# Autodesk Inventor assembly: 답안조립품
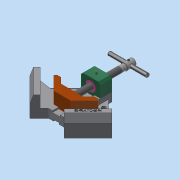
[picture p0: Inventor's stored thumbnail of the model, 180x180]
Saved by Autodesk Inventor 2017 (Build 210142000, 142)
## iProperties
Part Number: 답안조립품
Material: 일반
Document SubType Name: Assembly
Designer: 222
Author: 222
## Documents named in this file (11)
- C:\Users\222\Desktop\700506V1054\답안조립품.iam
- C:\Users\222\Desktop\700506V1054\본체.ipt
- C:\Users\222\Desktop\700506V1054\리드스크류.ipt
- C:\Users\222\Desktop\700506V1054\멈춤나사 M4x5.ipt
- C:\Users\222\Desktop\700506V1054\멈춤나사 M4x10.ipt
- C:\Users\222\Desktop\700506V1054\볼트 M4x16.ipt
- C:\Users\222\Desktop\700506V1054\부시.ipt
- C:\Users\222\Desktop\700506V1054\서포트.ipt
- C:\Users\222\Desktop\700506V1054\조.ipt
- C:\Users\222\Desktop\700506V1054\평행 핀 2.5x24.ipt
- C:\Users\222\Desktop\700506V1054\핸들.ipt
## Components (1 placed, 1 different names)
1. 핸들:1 — 각도:1
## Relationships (1: Angle 1)
- 각도:1 [Angle]: 핸들:1
